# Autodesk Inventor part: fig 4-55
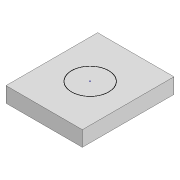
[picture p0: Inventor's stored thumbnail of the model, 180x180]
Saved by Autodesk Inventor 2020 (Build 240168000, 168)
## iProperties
Created: 2019-07
Part Number: fig 4-55
Material: Generic
Document SubType Name: Modeling
Designer: LENOVO-CADCIM
Density: 1 g/cm^3
Appearance: Default
Author: LENOVO-CADCIM
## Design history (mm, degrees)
sketch "Sketch1"
  geometry: L1 (-12.5, 15)-(12.5, 15); L2 (12.5, 15)-(12.5, -15); L3 (12.5, -15)-(-12.5, -15); L4 (-12.5, -15)-(-12.5, 15); L5 (-12.5, 15)-(12.5, -15); L6 (12.5, 15)-(-12.5, -15); 1 further point
  constraints: 12 end point, 2 midpoint, 2 parallel, 1 horizontal, 1 perpendicular
  dimensions: "d0" = 30 distance of L3.end L1.start; "d1" = 25 distance of L2.end L3.end
extrude "Extrusion1" new body sketch "Sketch1" distance "d2" = 5; taper "d3" = 0 deg
sketch "Sketch2"
  geometry: C1 r 6.058 at (0, 0); 1 further point
  constraints: 1 centre point, 1 coincident
body "Solid1"
